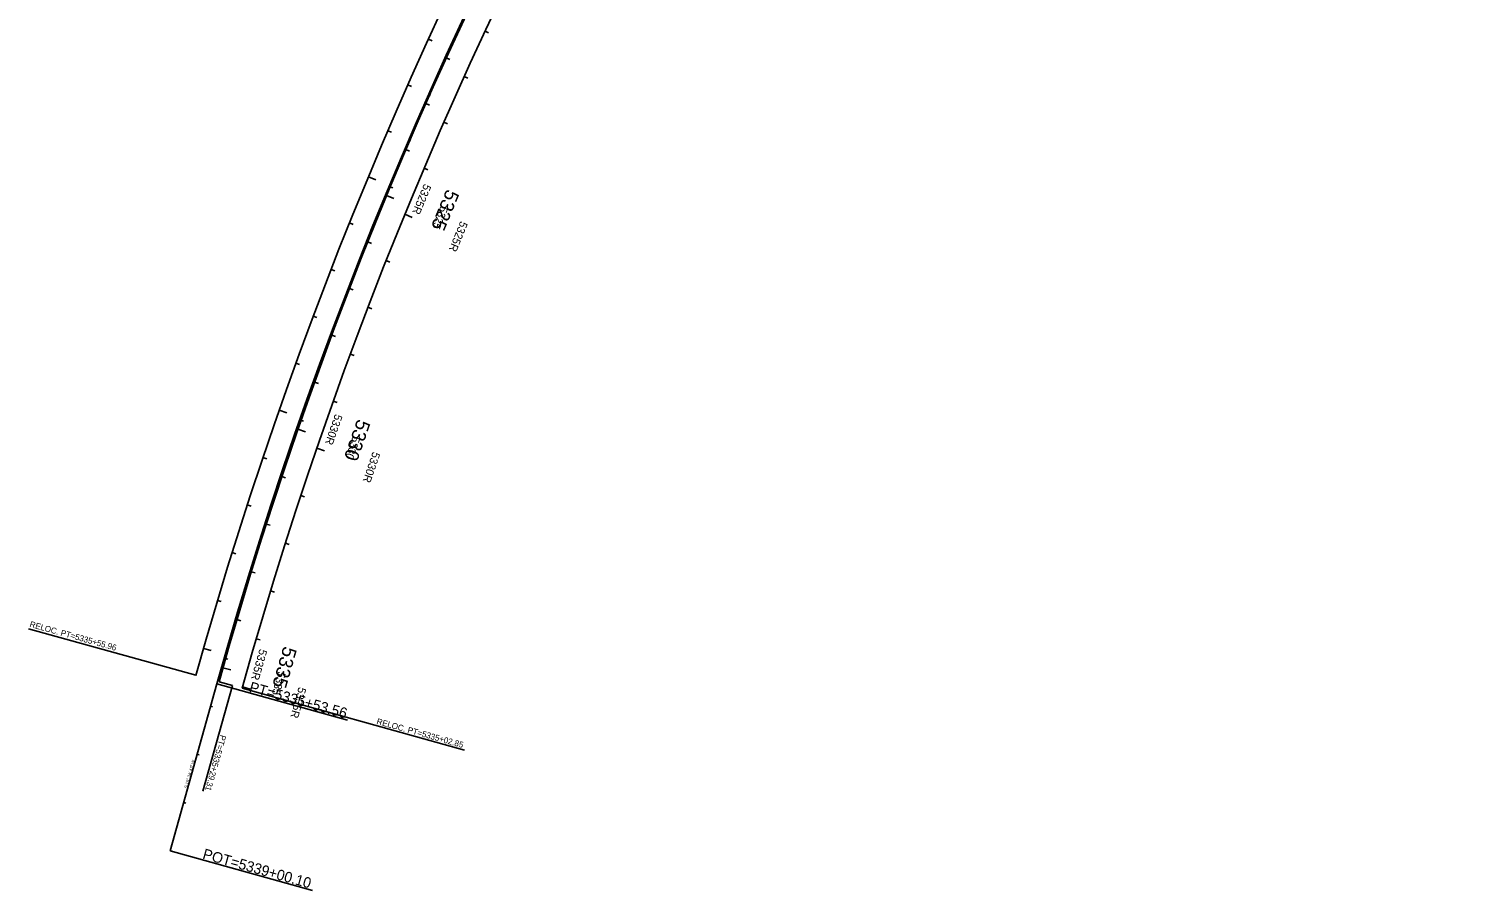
# Model space of a CAD drawing. Extents: x 2160876 to 2175990, y 601436 to 618246.
# Drawn here: x 2160876 to 2163737, y 601436 to 603160 of the extents above; entities that cross this region are included whole.
import ezdxf

# ---------------------------------------------------------------- set-up
doc = ezdxf.new("R2010")
doc.units = 0
for name, color, linetype in [('BNDY-ADJ', 7, 'Continuous'), ('BNDY-ADJ-TXT', 7, 'Continuous'), ('RD_DTM_Major2', 7, 'Continuous'), ('RD_EX_BldgApp_Steps', 7, 'Continuous'), ('RD_EX_DV_TX_Prop', 7, 'Continuous'), ('RD_EX_Parking_Conc', 7, 'Continuous'), ('RD_HC_Cl', 7, 'Continuous'), ('RD_HC_Data_Tic', 7, 'Continuous'), ('RD_HC_TX_Sta50', 7, 'Continuous')]:
    doc.layers.add(name, color=color, linetype=linetype)

msp = doc.modelspace()

# ---------------------------------------------------------------- linework, layer by layer
at = {"layer": 'BNDY-ADJ'}
msp.add_arc((2169535, 599544.7), 8593.9, 132.71947, 164.41949, dxfattribs=at)
at = {"layer": 'BNDY-ADJ-TXT'}
for radius in [8641.9, 8545.9]:
    msp.add_arc((2169535, 599544.7), radius, 132.71947, 164.41949, dxfattribs=at)
at = {"layer": 'RD_DTM_Major2'}
for p, q in [((2161711.3, 603100.8), (2161718.6, 603097.5)), ((2161670.5, 603009.5), (2161677.8, 603006.3)), ((2161630.7, 602917.8), (2161638.1, 602914.6)), ((2161592, 602825.6), (2161606.8, 602819.5)), ((2161554.3, 602732.9), (2161561.8, 602730)), ((2161517.8, 602639.9), (2161525.2, 602637)), ((2161482.3, 602546.4), (2161489.8, 602543.6)), ((2161447.9, 602452.5), (2161455.5, 602449.7)), ((2161414.6, 602358.2), (2161429.8, 602352.9)), ((2161382.5, 602263.5), (2161390, 602260.9)), ((2161351.4, 602168.4), (2161359, 602166)), ((2161321.4, 602073), (2161329, 602070.7)), ((2161292.5, 601977.3), (2161300.2, 601975)), ((2161264.8, 601881.2), (2161280.2, 601876.9))]:
    msp.add_line(p, q, dxfattribs=at)
at = {"layer": 'RD_EX_BldgApp_Steps'}
for p, q in [((2161717.1, 603118.7), (2161720.7, 603117.1)), ((2161676, 603027.6), (2161679.6, 603025.9)), ((2161635.9, 602935.9), (2161639.6, 602934.4)), ((2161597, 602843.8), (2161604.4, 602840.8)), ((2161559.1, 602751.3), (2161562.8, 602749.8)), ((2161522.3, 602658.3), (2161526, 602656.9)), ((2161486.5, 602564.9), (2161490.3, 602563.5)), ((2161451.9, 602471.1), (2161455.6, 602469.8)), ((2161418.3, 602376.9), (2161425.9, 602374.3)), ((2161385.9, 602282.3), (2161389.7, 602281.1)), ((2161354.5, 602187.4), (2161358.3, 602186.1)), ((2161324.3, 602092.1), (2161328.1, 602090.9)), ((2161295.2, 601996.4), (2161299, 601995.2)), ((2161267.2, 601900.4), (2161274.8, 601898.2)), ((2161252.6, 601848.8), (2161159.5, 601515)), ((2161252.6, 601848.8), (2161513.5, 601776.1)), ((2161240.1, 601804.1), (2161244, 601803)), ((2161213.3, 601707.8), (2161217.1, 601706.7)), ((2161186.4, 601611.5), (2161190.3, 601610.4)), ((2161159.5, 601515), (2161444, 601435.7)), ((2161159.6, 601515.1), (2161163.4, 601514.1))]:
    msp.add_line(p, q, dxfattribs=at)
msp.add_arc((2169530.8, 599540.9), 8593.9, 132.71947, 164.42145, dxfattribs=at)
at = {"layer": 'RD_EX_Parking_Conc'}
for p, q in [((2161283.6, 601845.5), (2161224.7, 601634.4)), ((2161256.9, 601853), (2161283.6, 601845.5))]:
    msp.add_line(p, q, dxfattribs=at)
at = {"layer": 'RD_HC_Cl'}
for p, q in [((2161788.9, 603154.5), (2161796.1, 603151.1)), ((2161675.6, 603138.2), (2161682.9, 603134.8)), ((2161634.5, 603047), (2161641.9, 603043.7)), ((2161747.2, 603063.6), (2161754.5, 603060.3)), ((2161594.6, 602955.3), (2161601.9, 602952.2)), ((2161706.5, 602972.2), (2161713.9, 602969)), ((2161667, 602880.4), (2161674.3, 602877.3)), ((2161555.6, 602863.2), (2161570.4, 602857.1)), ((2161628.5, 602788.1), (2161643.3, 602782)), ((2161517.8, 602770.7), (2161525.2, 602767.7)), ((2161591, 602695.4), (2161598.5, 602692.4)), ((2161481, 602677.7), (2161488.4, 602674.8)), ((2161445.2, 602584.3), (2161452.7, 602581.5)), ((2161554.7, 602602.2), (2161562.2, 602599.3)), ((2161519.5, 602508.6), (2161527, 602505.8)), ((2161410.6, 602490.5), (2161418.1, 602487.7)), ((2161485.4, 602414.6), (2161492.9, 602411.9)), ((2161377.1, 602396.2), (2161392.2, 602391)), ((2161344.6, 602301.7), (2161352.2, 602299.1)), ((2161452.3, 602320.2), (2161467.5, 602315)), ((2161420.4, 602225.5), (2161428, 602222.9)), ((2161313.3, 602206.7), (2161320.9, 602204.2)), ((2161389.6, 602130.3), (2161397.2, 602127.9)), ((2161283, 602111.4), (2161290.7, 602109)), ((2161253.9, 602015.7), (2161261.5, 602013.4)), ((2161359.9, 602034.8), (2161367.6, 602032.5)), ((2161331.3, 601939), (2161339, 601936.8)), ((2161225.8, 601919.7), (2161241.2, 601915.3)), ((2161303.9, 601842.8), (2161319.3, 601838.5))]:
    msp.add_line(p, q, dxfattribs=at)
at = {"layer": 'RD_HC_TX_Sta50'}
for p, q in [((2160876.1, 601959.2), (2161210.6, 601865.9)), ((2161303.1, 601840.1), (2161747.5, 601716.2))]:
    msp.add_line(p, q, dxfattribs=at)

# ---------------------------------------------------------------- texts
at = {"layer": 'RD_EX_BldgApp_Steps'}
for s, height, rotation, p in [('5325', 28, 247.3974, (2161712.3, 602839.9)), ('5330', 28, 250.7309, (2161533.8, 602379.8)), ('5335', 28, 254.0644, (2161386.1, 601925.5)), ('PT=5335+53.56', 21, 344.4214, (2161315.8, 601833.3)), ('S 15° 34\' 43" W', 6, 74.4214, (2161193.2, 601639.6)), ('POT=5339+00.10', 21, 344.4214, (2161222.7, 601499.5))]:
    msp.add_text(s, height=height, rotation=rotation, dxfattribs=at).set_placement(p)
at = {"layer": 'RD_EX_DV_TX_Prop'}
for s, rotation, p in [('5325', 247.5571, (2161700.8, 602806.2)), ('5330', 250.8906, (2161524.6, 602345.6)), ('5335', 254.2241, (2161375.2, 601874.6))]:
    msp.add_text(s, height=16, rotation=rotation, dxfattribs=at).set_placement(p)
at = {"layer": 'RD_EX_Parking_Conc'}
msp.add_text('PT=5335+29.31', height=12, rotation=254.4195, dxfattribs=at).set_placement((2161259.8, 601747.6))
at = {"layer": 'RD_HC_Data_Tic'}
for s, rotation, p in [('5325R', 247.4185, (2161667.1, 602850.1)), ('5325R', 247.6959, (2161740, 602775.6)), ('5330R', 250.7335, (2161489.2, 602389.6)), ('5330R', 251.0482, (2161564.5, 602314.2)), ('5335R', 254.0485, (2161338.1, 601919.6)), ('5335R', 254.4004, (2161416.2, 601843.4))]:
    msp.add_text(s, height=16, rotation=rotation, dxfattribs=at).set_placement(p)
at = {"layer": 'RD_HC_TX_Sta50'}
for s, p in [('RELOC. PT=5335+55.96', (2160877.2, 601963)), ('RELOC. PT=5335+02.85', (2161571, 601768.7))]:
    msp.add_text(s, height=12, rotation=344.4195, dxfattribs=at).set_placement(p)

doc.saveas('drawing.dxf')
